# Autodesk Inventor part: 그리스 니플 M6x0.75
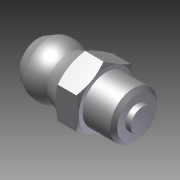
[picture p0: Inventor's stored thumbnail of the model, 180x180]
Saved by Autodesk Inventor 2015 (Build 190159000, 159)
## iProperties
Created: 2024-12
Part Number: 그리스 니플 M6x0.75
Material: 일반
Document SubType Name: Modeling
Designer: 102566
Density: 1 g/cm^3
Appearance: 기본값
Author: 102566
Author: jhkim
Description: 윤활 니플, 원추 유형 A
Creation Date: 2024-11-28
Sending System: Autodesk Inventor 2025
Preprocessor: ST-DEVELOPER v20
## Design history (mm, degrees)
node "그리스 니플 M6x0.751"
body "Solid1"
node "기준1"
